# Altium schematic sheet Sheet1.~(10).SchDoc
size A4; SheetNumber: 2; SheetTotal: 2
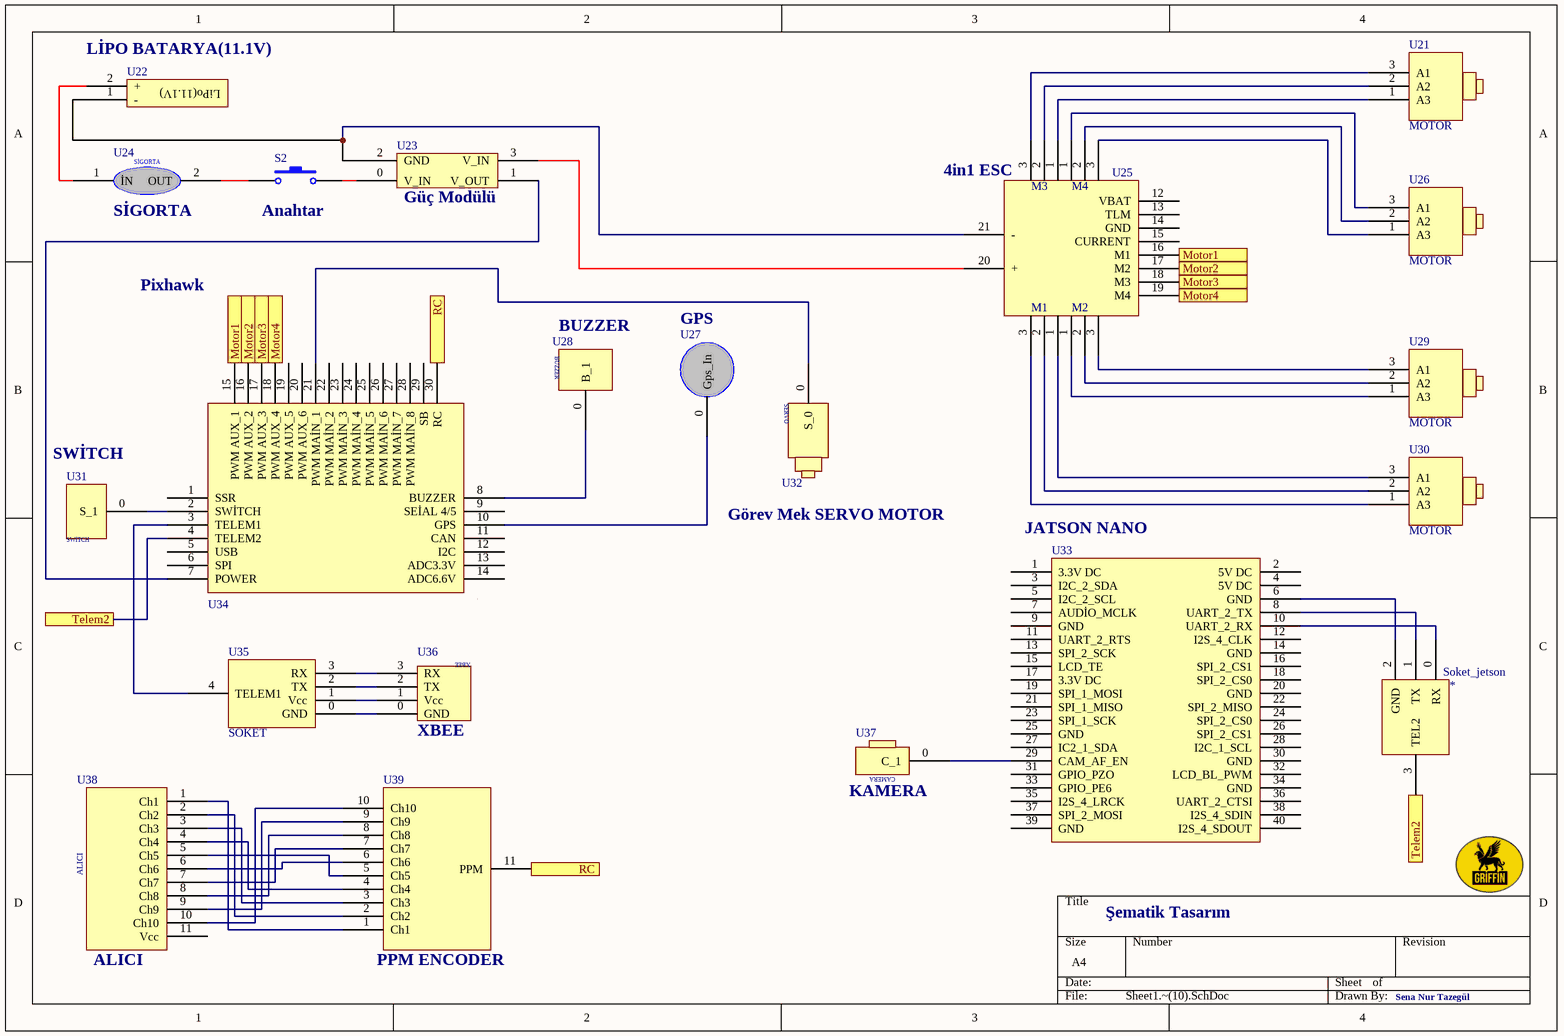
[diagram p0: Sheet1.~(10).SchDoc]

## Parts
*  Soket_jetson
S2  Anahtar  [SPST-2]
U21  MOTOR
U22  LİPO BATARYA(11.1V)
U23  (no value)
U24  SİGORTA
U25  4in1 ESC
U26  MOTOR
U27  GPS
U28  BUZZER
U29  MOTOR
U30  MOTOR
U31  SWİTCH
U32  Görev Mek SERVO MOTOR
U33  JATSON NANO
U34  Pixhawk
U35  SOKET
U36  XBEE
U37  KAMERA
U38  ALICI
U39  PPM ENCODER

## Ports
Motor1, Motor2, Motor3, Motor4, RC, Telem2

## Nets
Motor1: U25.16(M1) U34.15(PWM_AUX_1) ; port Motor1
Motor2: U25.17(M2) U34.16(PWM_AUX_2) ; port Motor2
Motor3: U25.18(M3) U34.17(PWM_AUX_3) ; port Motor3
Motor4: U25.19(M4) U34.18(PWM_AUX_4) ; port Motor4
RC: U34.30(RC) U39.11(PPM) ; port RC
Telem2: *.3(TEL2) U34.4(TELEM2) ; port Telem2
Net*_0: *.0(RX) U33.10(UART_2_RX)
Net*_1: *.1(TX) U33.8(UART_2_TX)
Net*_2: *.2(GND) U33.6(GND)
NetS2_1: S2.1 U24.2(OUT)
NetS2_2: S2.2 U23.0(V_IN)
NetU21_1: U21.1(A3) U25.1
NetU21_2: U21.2(A2) U25.2
NetU21_3: U21.3(A1) U25.3
NetU22_1: U22.1(-) U23.2(GND) U25.21(-)
NetU22_2: U22.2(+) U24.1(İN)
NetU23_1: U23.1(V_OUT) U34.7(POWER)
NetU23_3: U23.3(V_IN) U25.20(+)
NetU25_1: U25.1 U29.1(A3)
NetU25_1: U25.1 U30.3(A1)  [a separate net that carries the same name]
NetU25_1: U25.1 U26.3(A1)  [a separate net that carries the same name]
NetU25_2: U25.2 U29.2(A2)
NetU25_2: U25.2 U30.2(A2)  [a separate net that carries the same name]
NetU25_2: U25.2 U26.2(A2)  [a separate net that carries the same name]
NetU25_3: U25.3 U29.3(A1)
NetU25_3: U25.3 U30.1(A3)  [a separate net that carries the same name]
NetU25_3: U25.3 U26.1(A3)  [a separate net that carries the same name]
NetU27_0: U27.0(Gps_In) U34.10(GPS)
NetU28_0: U28.0(B_1) U34.8(BUZZER)
NetU31_0: U31.0(S_1) U34.2(SWİTCH)
NetU32_0: U32.0(S_0) U34.21(PWM_MAİN_1)
NetU33_29: U33.29(CAM_AF_EN) U37.0(C_1)
NetU34_3: U34.3(TELEM1) U35.4(TELEM1)
NetU35_0: U35.0(GND) U36.0(GND)
NetU35_1: U35.1(Vcc) U36.1(Vcc)
NetU35_2: U35.2(TX) U36.2(TX)
NetU35_3: U35.3(RX) U36.3(RX)
NetU38_1: U38.1(Ch1) U39.1(Ch1)
NetU38_2: U38.2(Ch2) U39.2(Ch2)
NetU38_3: U38.3(Ch3) U39.3(Ch3)
NetU38_4: U38.4(Ch4) U39.4(Ch4)
NetU38_5: U38.5(Ch5) U39.5(Ch5)
NetU38_6: U38.6(Ch6) U39.6(Ch6)
NetU38_7: U38.7(Ch7) U39.7(Ch7)
NetU38_8: U38.8(Ch8) U39.8(Ch8)
NetU38_9: U38.9(Ch9) U39.9(Ch9)
NetU38_10: U38.10(Ch10) U39.10(Ch10)

Not connected (* = marked no-connect by the designer): U25 12(VBAT) 13(TLM) 14(GND) 15(CURRENT); U33 1(3.3V_DC) 2(5V_DC) 3(I2C_2_SDA) 4(5V_DC) 5(I2C_2_SCL) 7(AUDİO_MCLK) 9(GND) 11(UART_2_RTS) 12(I2S_4_CLK) 13(SPI_2_SCK) 14(GND) 15(LCD_TE) 16(SPI_2_CS1) 17(3.3V_DC) 18(SPI_2_CS0) 19(SPI_1_MOSI) 20(GND) 21(SPI_1_MISO) 22(SPI_2_MISO) 23(SPI_1_SCK) 24(SPI_2_CS0) 25(GND) 26(SPI_2_CS1) 27(IC2_1_SDA) 28(I2C_1_SCL) 30(GND) 31(GPIO_PZO) 32(LCD_BL_PWM) 33(GPIO_PE6) 34(GND) 35(I2S_4_LRCK) 36(UART_2_CTSI) 37(SPI_2_MOSI) 38(I2S_4_SDIN) 39(GND) 40(I2S_4_SDOUT); U34 1(SSR) 5(USB) 6(SPI) 9(SEİAL_4/5) 11(CAN) 12(I2C) 13(ADC3.3V) 14(ADC6.6V) 19(PWM_AUX_5) 20(PWM_AUX_6) 22(PWM_MAİN_2) 23(PWM_MAİN_3) 24(PWM_MAİN_4) 25(PWM_MAİN_5) 26(PWM_MAİN_6) 27(PWM_MAİN_7) 28(PWM_MAİN_8) 29(SB); U38 11(Vcc)

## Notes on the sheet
- Şematik Tasarım
- Sena Nur Tazegül

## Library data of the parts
S2 = SW-PB: Switch
U23 = GÜÇ MODÜLÜ
U32 = SERVO MOTOR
